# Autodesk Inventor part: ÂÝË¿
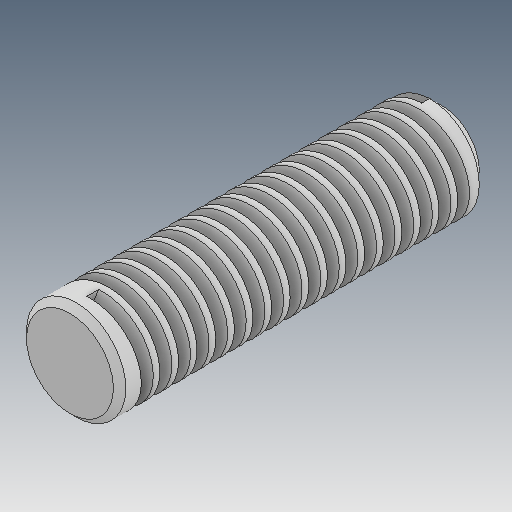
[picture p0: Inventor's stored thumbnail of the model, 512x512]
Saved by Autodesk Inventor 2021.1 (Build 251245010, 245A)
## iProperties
Created: 2019-04
Part Number: ÂÝË¿
Material: Ogólny
Document SubType Name: Modeling
Designer: user
Density: 1 g/cm^3
Appearance: Domyślna
Author: user
Revision Number: ÈÎºÎ
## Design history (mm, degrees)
feature "ÊäÈë1"
node "Bryła1"
